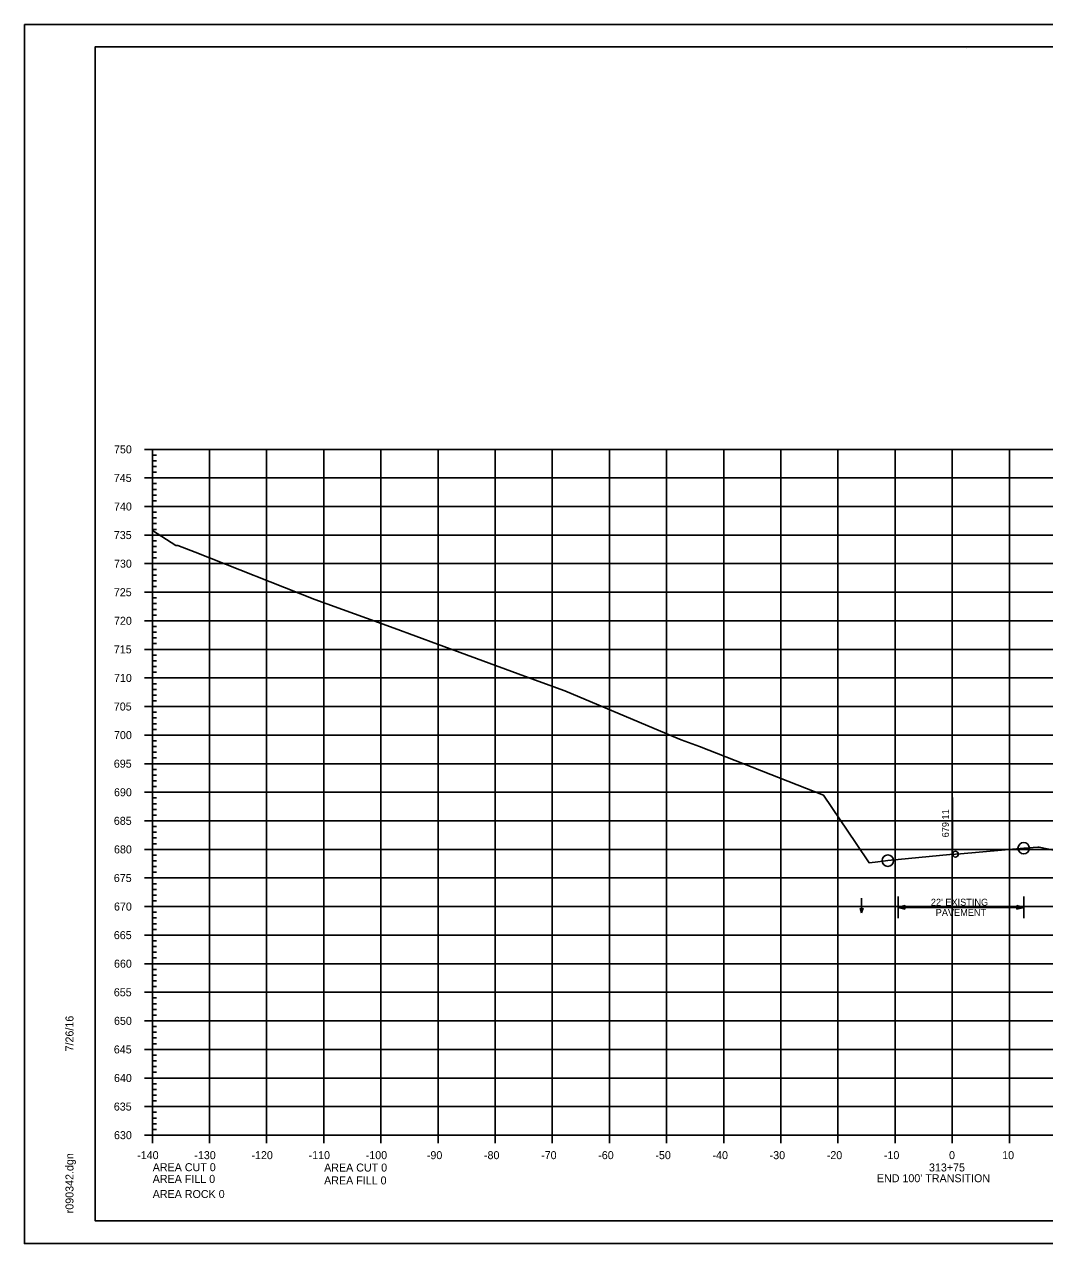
# Model space of a CAD drawing. Extents: x 1370515 to 1370849, y 383299 to 386073.
# Drawn here: x 1370515.4 to 1370694, y 385859.5 to 386072.8 of the extents above; entities that cross this region are included whole.
import ezdxf

# ---------------------------------------------------------------- set-up
doc = ezdxf.new("R2010")
doc.units = 0
for name, color, linetype in [('R_Axis', 7, 'Continuous'), ('R_Axis Annot', 7, 'Continuous'), ('R_Border', 7, 'Continuous'), ('R_Exist Surface', 7, 'Continuous'), ('R_Grid', 7, 'Continuous'), ('R_No Plot', 7, 'Continuous'), ('R_ROW Annot', 7, 'Continuous'), ('R_Water Annot', 7, 'Continuous'), ('R_Xsect Elev', 7, 'Continuous')]:
    doc.layers.add(name, color=color, linetype=linetype)

msp = doc.modelspace()

# ---------------------------------------------------------------- linework, layer by layer
at = {"layer": 'R_Axis'}
for p, q in [((1370536.4, 385998.46), (1370539.2, 385998.46)), ((1370537.8, 385878.46), (1370537.8, 385998.46)), ((1370537.8, 385997.46), (1370538.5, 385997.46)), ((1370537.8, 385996.46), (1370538.5, 385996.46)), ((1370537.8, 385995.46), (1370538.5, 385995.46)), ((1370537.8, 385994.46), (1370538.5, 385994.46)), ((1370536.4, 385993.46), (1370539.2, 385993.46)), ((1370537.8, 385992.46), (1370538.5, 385992.46)), ((1370537.8, 385991.46), (1370538.5, 385991.46)), ((1370537.8, 385990.46), (1370538.5, 385990.46)), ((1370536.4, 385988.46), (1370539.2, 385988.46)), ((1370537.8, 385989.46), (1370538.5, 385989.46)), ((1370537.8, 385987.46), (1370538.5, 385987.46)), ((1370537.8, 385986.46), (1370538.5, 385986.46)), ((1370537.8, 385985.46), (1370538.5, 385985.46)), ((1370536.4, 385983.46), (1370539.2, 385983.46)), ((1370537.8, 385984.46), (1370538.5, 385984.46)), ((1370537.8, 385982.46), (1370538.5, 385982.46)), ((1370537.8, 385981.46), (1370538.5, 385981.46)), ((1370537.8, 385980.46), (1370538.5, 385980.46)), ((1370537.8, 385979.46), (1370538.5, 385979.46)), ((1370536.4, 385978.46), (1370539.2, 385978.46)), ((1370537.8, 385977.46), (1370538.5, 385977.46)), ((1370537.8, 385976.46), (1370538.5, 385976.46)), ((1370537.8, 385975.46), (1370538.5, 385975.46)), ((1370536.4, 385973.46), (1370539.2, 385973.46)), ((1370537.8, 385974.46), (1370538.5, 385974.46)), ((1370537.8, 385972.46), (1370538.5, 385972.46)), ((1370537.8, 385971.46), (1370538.5, 385971.46)), ((1370537.8, 385970.46), (1370538.5, 385970.46)), ((1370536.4, 385968.46), (1370539.2, 385968.46)), ((1370537.8, 385969.46), (1370538.5, 385969.46)), ((1370537.8, 385967.46), (1370538.5, 385967.46)), ((1370537.8, 385966.46), (1370538.5, 385966.46)), ((1370537.8, 385965.46), (1370538.5, 385965.46)), ((1370537.8, 385964.46), (1370538.5, 385964.46)), ((1370536.4, 385963.46), (1370539.2, 385963.46)), ((1370537.8, 385962.46), (1370538.5, 385962.46)), ((1370537.8, 385961.46), (1370538.5, 385961.46)), ((1370537.8, 385960.46), (1370538.5, 385960.46)), ((1370536.4, 385958.46), (1370539.2, 385958.46)), ((1370537.8, 385959.46), (1370538.5, 385959.46)), ((1370537.8, 385957.46), (1370538.5, 385957.46)), ((1370537.8, 385956.46), (1370538.5, 385956.46)), ((1370537.8, 385955.46), (1370538.5, 385955.46)), ((1370536.4, 385953.46), (1370539.2, 385953.46)), ((1370537.8, 385954.46), (1370538.5, 385954.46)), ((1370537.8, 385952.46), (1370538.5, 385952.46)), ((1370537.8, 385951.46), (1370538.5, 385951.46)), ((1370537.8, 385950.46), (1370538.5, 385950.46)), ((1370537.8, 385949.46), (1370538.5, 385949.46)), ((1370536.4, 385948.46), (1370539.2, 385948.46)), ((1370537.8, 385947.46), (1370538.5, 385947.46)), ((1370537.8, 385946.46), (1370538.5, 385946.46)), ((1370537.8, 385945.46), (1370538.5, 385945.46)), ((1370536.4, 385943.46), (1370539.2, 385943.46)), ((1370537.8, 385944.46), (1370538.5, 385944.46)), ((1370537.8, 385942.46), (1370538.5, 385942.46)), ((1370537.8, 385941.46), (1370538.5, 385941.46)), ((1370536.4, 385938.46), (1370539.2, 385938.46)), ((1370537.8, 385940.46), (1370538.5, 385940.46)), ((1370537.8, 385939.46), (1370538.5, 385939.46)), ((1370537.8, 385937.46), (1370538.5, 385937.46)), ((1370537.8, 385936.46), (1370538.5, 385936.46)), ((1370537.8, 385935.46), (1370538.5, 385935.46)), ((1370537.8, 385934.46), (1370538.5, 385934.46)), ((1370536.4, 385933.46), (1370539.2, 385933.46)), ((1370537.8, 385932.46), (1370538.5, 385932.46)), ((1370537.8, 385931.46), (1370538.5, 385931.46)), ((1370537.8, 385930.46), (1370538.5, 385930.46)), ((1370536.4, 385928.46), (1370539.2, 385928.46)), ((1370537.8, 385929.46), (1370538.5, 385929.46)), ((1370537.8, 385927.46), (1370538.5, 385927.46)), ((1370537.8, 385926.46), (1370538.5, 385926.46)), ((1370536.4, 385923.46), (1370539.2, 385923.46)), ((1370537.8, 385925.46), (1370538.5, 385925.46)), ((1370537.8, 385924.46), (1370538.5, 385924.46)), ((1370537.8, 385922.46), (1370538.5, 385922.46)), ((1370537.8, 385921.46), (1370538.5, 385921.46)), ((1370537.8, 385920.46), (1370538.5, 385920.46)), ((1370537.8, 385919.46), (1370538.5, 385919.46)), ((1370536.4, 385918.46), (1370539.2, 385918.46)), ((1370537.8, 385917.46), (1370538.5, 385917.46)), ((1370537.8, 385916.46), (1370538.5, 385916.46)), ((1370537.8, 385915.46), (1370538.5, 385915.46)), ((1370536.4, 385913.46), (1370539.2, 385913.46)), ((1370537.8, 385914.46), (1370538.5, 385914.46)), ((1370537.8, 385912.46), (1370538.5, 385912.46)), ((1370537.8, 385911.46), (1370538.5, 385911.46)), ((1370537.8, 385910.46), (1370538.5, 385910.46)), ((1370537.8, 385909.46), (1370538.5, 385909.46)), ((1370536.4, 385908.46), (1370539.2, 385908.46)), ((1370537.8, 385907.46), (1370538.5, 385907.46)), ((1370537.8, 385906.46), (1370538.5, 385906.46)), ((1370537.8, 385905.46), (1370538.5, 385905.46)), ((1370537.8, 385904.46), (1370538.5, 385904.46)), ((1370536.4, 385903.46), (1370539.2, 385903.46)), ((1370537.8, 385902.46), (1370538.5, 385902.46)), ((1370537.8, 385901.46), (1370538.5, 385901.46)), ((1370537.8, 385900.46), (1370538.5, 385900.46)), ((1370536.4, 385898.46), (1370539.2, 385898.46)), ((1370537.8, 385899.46), (1370538.5, 385899.46)), ((1370537.8, 385897.46), (1370538.5, 385897.46)), ((1370537.8, 385896.46), (1370538.5, 385896.46)), ((1370537.8, 385895.46), (1370538.5, 385895.46)), ((1370537.8, 385894.46), (1370538.5, 385894.46)), ((1370536.4, 385893.46), (1370539.2, 385893.46)), ((1370537.8, 385892.46), (1370538.5, 385892.46)), ((1370537.8, 385891.46), (1370538.5, 385891.46)), ((1370537.8, 385890.46), (1370538.5, 385890.46)), ((1370537.8, 385889.46), (1370538.5, 385889.46)), ((1370536.4, 385888.46), (1370539.2, 385888.46)), ((1370537.8, 385887.46), (1370538.5, 385887.46)), ((1370537.8, 385886.46), (1370538.5, 385886.46)), ((1370537.8, 385885.46), (1370538.5, 385885.46)), ((1370536.4, 385883.46), (1370539.2, 385883.46)), ((1370537.8, 385884.46), (1370538.5, 385884.46)), ((1370537.8, 385882.46), (1370538.5, 385882.46)), ((1370537.8, 385881.46), (1370538.5, 385881.46)), ((1370537.8, 385880.46), (1370538.5, 385880.46)), ((1370537.8, 385877.06), (1370537.8, 385879.86)), ((1370537.8, 385879.46), (1370538.5, 385879.46)), ((1370547.8, 385877.06), (1370547.8, 385879.86)), ((1370557.8, 385877.06), (1370557.8, 385879.86)), ((1370567.8, 385877.06), (1370567.8, 385879.86)), ((1370577.8, 385877.06), (1370577.8, 385879.86)), ((1370587.8, 385877.06), (1370587.8, 385879.86)), ((1370597.8, 385877.06), (1370597.8, 385879.86)), ((1370607.8, 385877.06), (1370607.8, 385879.86)), ((1370617.8, 385877.06), (1370617.8, 385879.86)), ((1370627.8, 385877.06), (1370627.8, 385879.86)), ((1370637.8, 385877.06), (1370637.8, 385879.86)), ((1370647.8, 385877.06), (1370647.8, 385879.86)), ((1370657.8, 385877.06), (1370657.8, 385879.86)), ((1370667.8, 385877.06), (1370667.8, 385879.86)), ((1370677.8, 385877.06), (1370677.8, 385879.86)), ((1370687.8, 385877.06), (1370687.8, 385879.86)), ((1370536.4, 385878.46), (1370539.2, 385878.46)), ((1370537.8, 385878.46), (1370817.8, 385878.46))]:
    msp.add_line(p, q, dxfattribs=at)
at = {"layer": 'R_Border'}
for p, q in [((1370527.8, 386068.92), (1370843.98, 386068.92)), ((1370527.8, 385863.46), (1370527.8, 386068.92)), ((1370680.32, 386068.66), (1370680.32, 386068.66)), ((1370680.32, 386068.66), (1370680.32, 386068.66)), ((1370527.8, 385863.46), (1370527.8, 385863.46)), ((1370843.98, 385863.46), (1370527.8, 385863.46))]:
    msp.add_line(p, q, dxfattribs=at)
at = {"layer": 'R_Exist Surface'}
msp.add_lwpolyline([(1370537.8, 385984.24), (1370541.88, 385981.64), (1370542.24, 385981.64), (1370545.28, 385980.45), (1370566.25, 385972.18), (1370580.13, 385967.16), (1370587.72, 385964.38), (1370604.71, 385958.11), (1370609.97, 385956.18), (1370628.94, 385948.2), (1370630.34, 385947.61), (1370633.54, 385946.44), (1370655.28, 385937.93), (1370660.99, 385929.5), (1370663.24, 385926.11), (1370663.78, 385926.17), (1370664.31, 385926.23), (1370666.11, 385926.44), (1370666.52, 385926.49), (1370677.36, 385927.54), (1370678.36, 385927.63), (1370679.26, 385927.71), (1370690.31, 385928.66), (1370692.8, 385928.84), (1370692.99, 385928.85), (1370695.8, 385928.27)], dxfattribs=at)
at = {"layer": 'R_Grid'}
for p, q in [((1370537.8, 385998.46), (1370817.8, 385998.46)), ((1370537.8, 385878.46), (1370537.8, 385998.46)), ((1370547.8, 385878.46), (1370547.8, 385998.46)), ((1370557.8, 385878.46), (1370557.8, 385998.46)), ((1370567.8, 385878.46), (1370567.8, 385998.46)), ((1370577.8, 385878.46), (1370577.8, 385998.46)), ((1370587.8, 385878.46), (1370587.8, 385998.46)), ((1370597.8, 385878.46), (1370597.8, 385998.46)), ((1370607.8, 385878.46), (1370607.8, 385998.46)), ((1370617.8, 385878.46), (1370617.8, 385998.46)), ((1370627.8, 385878.46), (1370627.8, 385998.46)), ((1370637.8, 385878.46), (1370637.8, 385998.46)), ((1370647.8, 385878.46), (1370647.8, 385998.46)), ((1370657.8, 385878.46), (1370657.8, 385998.46)), ((1370667.8, 385878.46), (1370667.8, 385998.46)), ((1370677.8, 385878.46), (1370677.8, 385998.46)), ((1370687.8, 385878.46), (1370687.8, 385998.46)), ((1370537.8, 385993.46), (1370817.8, 385993.46)), ((1370537.8, 385988.46), (1370817.8, 385988.46)), ((1370537.8, 385983.46), (1370817.8, 385983.46)), ((1370537.8, 385978.46), (1370817.8, 385978.46)), ((1370537.8, 385973.46), (1370817.8, 385973.46)), ((1370537.8, 385968.46), (1370817.8, 385968.46)), ((1370537.8, 385963.46), (1370817.8, 385963.46)), ((1370537.8, 385958.46), (1370817.8, 385958.46)), ((1370537.8, 385953.46), (1370817.8, 385953.46)), ((1370537.8, 385948.46), (1370817.8, 385948.46)), ((1370537.8, 385943.46), (1370817.8, 385943.46)), ((1370537.8, 385938.46), (1370817.8, 385938.46)), ((1370537.8, 385933.46), (1370817.8, 385933.46)), ((1370537.8, 385928.46), (1370817.8, 385928.46)), ((1370537.8, 385923.46), (1370817.8, 385923.46)), ((1370537.8, 385918.46), (1370817.8, 385918.46)), ((1370537.8, 385913.46), (1370817.8, 385913.46)), ((1370537.8, 385908.46), (1370817.8, 385908.46)), ((1370537.8, 385903.46), (1370817.8, 385903.46)), ((1370537.8, 385898.46), (1370817.8, 385898.46)), ((1370537.8, 385893.46), (1370817.8, 385893.46)), ((1370537.8, 385888.46), (1370817.8, 385888.46)), ((1370537.8, 385883.46), (1370817.8, 385883.46)), ((1370537.8, 385878.46), (1370817.8, 385878.46))]:
    msp.add_line(p, q, dxfattribs=at)
at = {"layer": 'R_No Plot'}
for p, q in [((1370515.4, 386072.82), (1370848.73, 386072.82)), ((1370515.4, 385859.49), (1370848.73, 385859.49))]:
    msp.add_line(p, q, dxfattribs=at)
for points in [[(1370515.39, 386072.82), (1370848.73, 386072.82), (1370848.73, 385859.48), (1370515.39, 385859.48)], [(1370761.72, 386068.92), (1370761.72, 386059.04), (1370797.45, 386059.04), (1370797.45, 386056.12), (1370820.65, 386056.12), (1370820.65, 386032.91), (1370843.98, 386032.91), (1370843.98, 385863.46), (1370527.8, 385863.46), (1370527.8, 386068.92)]]:
    msp.add_lwpolyline(points, close=True, dxfattribs=at)
for centre, radius in [((1370678.36, 385927.63), 0.5), ((1370690.31, 385928.66), 1), ((1370666.52, 385926.49), 1)]:
    msp.add_circle(centre, radius, dxfattribs=at)
at = {"layer": 'R_ROW Annot'}
for p, q in [((1370668.33, 385916.44), (1370668.33, 385920.2)), ((1370690.33, 385916.44), (1370690.33, 385920.2)), ((1370690.33, 385918.32), (1370668.33, 385918.32))]:
    msp.add_line(p, q, dxfattribs=at)
for points in [[(1370669.53, 385918.02), (1370668.33, 385918.32), (1370669.53, 385918.62)], [(1370689.13, 385918.62), (1370690.33, 385918.32), (1370689.13, 385918.02)]]:
    msp.add_lwpolyline(points, close=True, dxfattribs=at)
at = {"layer": 'R_Water Annot'}
for p, q in [((1370661.94, 385919.9), (1370661.94, 385917.39)), ((1370661.94, 385917.39), (1370661.66, 385918.16)), ((1370661.94, 385917.39), (1370662.22, 385918.16))]:
    msp.add_line(p, q, dxfattribs=at)
at = {"layer": 'R_Xsect Elev'}
for p, q in [((1370677.8, 385926.39), (1370677.8, 385936.39)), ((1370677.82, 385927.57), (1370677.82, 385937.57))]:
    msp.add_line(p, q, dxfattribs=at)

# ---------------------------------------------------------------- texts
at = {"layer": 'R_Axis'}
msp.add_text('-', height=0.0001, dxfattribs=at).set_placement((1370537.8, 385878.46))
at = {"layer": 'R_Axis Annot'}
for s, p in [('750', (1370531.08, 385997.76)), ('745', (1370531.05, 385992.76)), ('740', (1370531.08, 385987.76)), ('735', (1370531.05, 385982.76)), ('730', (1370531.08, 385977.76)), ('725', (1370531.05, 385972.76)), ('720', (1370531.08, 385967.76)), ('715', (1370531.05, 385962.76)), ('710', (1370531.08, 385957.76)), ('705', (1370531.05, 385952.76)), ('700', (1370531.08, 385947.76)), ('695', (1370531.05, 385942.76)), ('690', (1370531.08, 385937.76)), ('685', (1370531.05, 385932.76)), ('680', (1370531.08, 385927.76)), ('675', (1370531.05, 385922.76)), ('670', (1370531.08, 385917.76)), ('665', (1370531.05, 385912.76)), ('660', (1370531.08, 385907.76)), ('655', (1370531.05, 385902.76)), ('650', (1370531.08, 385897.76)), ('645', (1370531.05, 385892.76)), ('640', (1370531.08, 385887.76)), ('635', (1370531.05, 385882.76)), ('630', (1370531.08, 385877.76)), ('-140', (1370535.14, 385874.26)), ('-130', (1370545.14, 385874.26)), ('-120', (1370555.14, 385874.26)), ('-110', (1370565.14, 385874.26)), ('-100', (1370575.14, 385874.26)), ('-90', (1370585.84, 385874.26)), ('-80', (1370595.84, 385874.26)), ('-70', (1370605.84, 385874.26)), ('-60', (1370615.84, 385874.26)), ('-50', (1370625.84, 385874.26)), ('-40', (1370635.84, 385874.26)), ('-30', (1370645.84, 385874.26)), ('-20', (1370655.84, 385874.26)), ('-10', (1370665.84, 385874.26)), ('0', (1370677.24, 385874.26)), ('10', (1370686.54, 385874.26)), ('AREA CUT 0', (1370537.86, 385872.15)), ('AREA CUT 0', (1370567.86, 385872.09)), ('313+75', (1370673.73, 385872.11)), ('AREA FILL 0', (1370537.86, 385870.11)), ('AREA FILL 0', (1370567.86, 385869.84)), ("END 100' TRANSITION", (1370664.61, 385870.22)), ('AREA ROCK 0', (1370537.86, 385867.46))]:
    msp.add_text(s, height=1.4, dxfattribs=at).set_placement(p)
at = {"layer": 'R_Border'}
for s, p in [('7/26/16', (1370523.99, 385893.11)), ('r090342.dgn', (1370523.99, 385864.79))]:
    msp.add_text(s, height=1.4, rotation=90, dxfattribs=at).set_placement(p)
at = {"layer": 'R_No Plot'}
for p in [(1370542.2, 385981.59), (1370566.21, 385972.13), (1370587.67, 385964.33), (1370609.93, 385956.13), (1370630.3, 385947.56), (1370655.24, 385937.88), (1370663.2, 385926.06)]:
    msp.add_text('+', height=0.1, dxfattribs=at).set_placement(p)
at = {"layer": 'R_ROW Annot'}
for s, p in [("22' EXISTING", (1370674.06, 385918.62)), ('PAVEMENT', (1370674.91, 385916.82))]:
    msp.add_text(s, height=1.2, dxfattribs=at).set_placement(p)
at = {"layer": 'R_Xsect Elev'}
msp.add_text('679.11', height=1.2, rotation=90, dxfattribs=at).set_placement((1370677.22, 385930.57))

doc.saveas('drawing.dxf')
